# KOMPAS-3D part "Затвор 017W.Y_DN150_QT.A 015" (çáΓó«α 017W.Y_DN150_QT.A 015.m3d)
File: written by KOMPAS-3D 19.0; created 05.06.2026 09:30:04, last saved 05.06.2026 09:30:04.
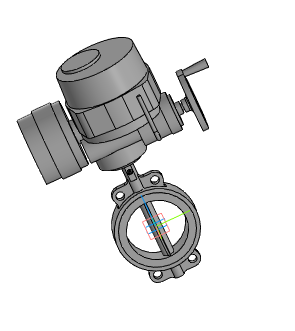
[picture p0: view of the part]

Document properties: Автор: Энергия; Полное имя файла: ..\..\..\3d для проектировщиков\x.x Тип 017W.Y(S) Затвор дисковый поворотный межфланцевый\Затвор 017W.Y(S)_DN32-DN1200_QT.A_MT903.A\Затвор 017W.Y_DN150_QT.A 015.a3d

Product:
- Part/product: Затвор 017W.Y_DN150_QT.A 015
    Масса: 98.5098

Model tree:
1. Операция без истории:1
